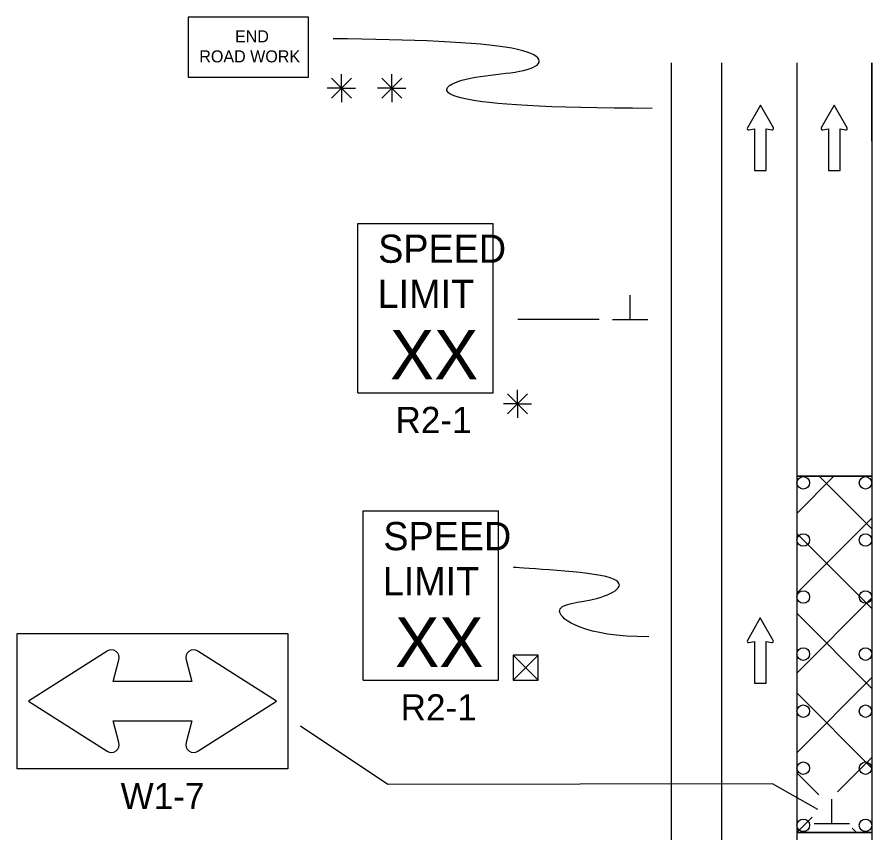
# Model space of a CAD drawing. Extents: x 16732 to 18482, y 5716 to 6919.
# Drawn here: x 16732 to 17004.7, y 6658.6 to 6919 of the extents above; entities that cross this region are included whole.
import ezdxf

# ---------------------------------------------------------------- set-up
doc = ezdxf.new("R2010")
doc.units = 0
for name, color, linetype in [('ALI_LEGAL_EX', 7, 'Continuous'), ('MT_SCRATCH_LEVEL_E', 7, 'Continuous'), ('PAVT_EDGE_EX', 7, 'Continuous'), ('TRAFFIC_SIGNS_PR', 7, 'Continuous'), ('TYPICAL_TEXT_DIMEN_PR', 7, 'Continuous')]:
    doc.layers.add(name, color=color, linetype=linetype)

msp = doc.modelspace()

# ---------------------------------------------------------------- linework, layer by layer
at = {"layer": 'ALI_LEGAL_EX'}
for p, q in [((16980.68, 6904.41), (16980.68, 6086.27)), ((17004.68, 6904.41), (17004.68, 6086.27))]:
    msp.add_line(p, q, dxfattribs=at)
for points in [[(16980.68, 6904.41), (16980.68, 6879.41)], [(17004.68, 6879.41), (17004.68, 6904.41)], [(17004.68, 6879.41), (17004.68, 6904.41)], [(16980.68, 6804.41), (16980.68, 6779.41)], [(17004.68, 6804.41), (17004.68, 6779.41)], [(16980.68, 6704.41), (16980.68, 6679.41)], [(17004.68, 6704.41), (17004.68, 6679.41)]]:
    msp.add_lwpolyline(points, dxfattribs=at)
at = {"layer": 'MT_SCRATCH_LEVEL_E'}
for p, q in [((16969.09, 6890.89), (16964.98, 6883.65)), ((16973.24, 6883.65), (16969.09, 6890.89)), ((16992.64, 6890.89), (16988.53, 6883.65)), ((16996.78, 6883.65), (16992.64, 6890.89)), ((16965.46, 6882.96), (16967.24, 6883.28)), ((16967.24, 6883.28), (16967.24, 6870.02)), ((16970.98, 6870.02), (16970.98, 6883.28)), ((16970.98, 6883.28), (16972.76, 6882.96)), ((16989.01, 6882.96), (16990.78, 6883.28)), ((16990.78, 6883.28), (16990.78, 6870.02)), ((16994.53, 6870.02), (16994.53, 6883.28)), ((16994.53, 6883.28), (16996.3, 6882.96)), ((16967.24, 6870.02), (16970.98, 6870.02)), ((16990.78, 6870.02), (16994.53, 6870.02)), ((16969.06, 6727.27), (16964.95, 6720.03)), ((16973.21, 6720.03), (16969.06, 6727.27)), ((16965.43, 6719.34), (16967.21, 6719.66)), ((16967.21, 6719.66), (16967.21, 6706.4)), ((16970.95, 6706.4), (16970.95, 6719.66)), ((16970.95, 6719.66), (16972.73, 6719.34)), ((16967.21, 6706.4), (16970.95, 6706.4))]:
    msp.add_line(p, q, dxfattribs=at)
for centre, start, end in [((16965.39, 6883.42), 150.4248, 279.9638), ((16972.83, 6883.42), 260.0362, 29.7731), ((16988.93, 6883.42), 150.4248, 279.9638), ((16996.37, 6883.42), 260.0362, 29.7731), ((16965.36, 6719.8), 150.4248, 279.9638), ((16972.8, 6719.8), 260.0362, 29.7731)]:
    msp.add_arc(centre, 0.463, start, end, dxfattribs=at)
at = {"layer": 'PAVT_EDGE_EX'}
for p, q in [((16940.68, 6904.41), (16940.68, 6086.27)), ((16956.68, 6904.41), (16956.68, 6086.27)), ((17004.68, 6772.46), (16980.68, 6772.46)), ((16980.68, 6772.46), (17004.68, 6772.46)), ((16980.68, 6772.46), (17004.68, 6772.46)), ((16980.68, 6760.56), (16992.58, 6772.46)), ((17004.68, 6755.65), (16987.87, 6772.46)), ((16980.68, 6735.1), (17004.68, 6759.1)), ((17004.68, 6730.19), (16980.68, 6754.19)), ((16980.68, 6709.64), (17004.68, 6733.64)), ((17004.68, 6704.74), (16980.68, 6728.74)), ((16980.68, 6684.19), (17004.68, 6708.19)), ((17004.68, 6679.28), (16980.68, 6703.28)), ((16993.7, 6671.75), (17004.68, 6682.73)), ((16987.74, 6670.76), (16980.68, 6677.82)), ((16980.68, 6658.73), (16985.57, 6663.63)), ((16999.77, 6658.73), (16998.36, 6660.14)), ((16980.68, 6658.73), (17004.68, 6658.73)), ((16980.68, 6658.73), (17004.68, 6658.73)), ((17004.68, 6658.73), (16980.68, 6658.73)), ((16980.68, 6658.73), (16980.68, 6658.73))]:
    msp.add_line(p, q, dxfattribs=at)
at = {"layer": 'TRAFFIC_SIGNS_PR'}
for p, q in [((16840.68, 6853.1), (16883.88, 6853.1)), ((16840.68, 6799.1), (16840.68, 6853.1)), ((16883.88, 6799.1), (16883.88, 6853.1)), ((16840.68, 6799.1), (16883.88, 6799.1)), ((16842.32, 6761.37), (16885.52, 6761.37)), ((16842.32, 6707.37), (16842.32, 6761.37)), ((16885.52, 6707.37), (16885.52, 6761.37)), ((16842.32, 6707.37), (16885.52, 6707.37))]:
    msp.add_line(p, q, dxfattribs=at)
for points in [[(16786.49, 6899.8), (16824.89, 6899.8), (16824.89, 6919), (16786.49, 6919)], [(16818.36, 6679.06), (16731.96, 6679.06), (16731.96, 6722.26), (16818.36, 6722.26)]]:
    msp.add_lwpolyline(points, close=True, dxfattribs=at)
for points in [[(16760.67, 6716.64), (16735.56, 6700.66), (16760.67, 6684.68)], [(16789.65, 6684.69), (16814.76, 6700.66), (16789.65, 6716.64)], [(16785.87, 6713.85), (16787.76, 6706.96), (16762.57, 6706.96), (16764.46, 6713.85)], [(16764.46, 6687.48), (16762.57, 6694.36), (16787.76, 6694.36), (16785.87, 6687.48)]]:
    msp.add_lwpolyline(points, dxfattribs=at)
for centre in [(16982.78, 6770.34), (17002.65, 6770.34), (16982.78, 6752.12), (17002.65, 6752.12), (16982.78, 6733.91), (17002.65, 6733.91), (16982.78, 6715.69), (17002.65, 6715.69), (16982.78, 6697.48), (17002.65, 6697.48), (16982.78, 6679.26), (17002.65, 6679.26), (16982.78, 6661.05), (17002.65, 6661.05)]:
    msp.add_circle(centre, 2, dxfattribs=at)
for centre, start, end in [((16762.03, 6714.51), 344.6731, 122.4696), ((16788.3, 6714.51), 57.5304, 195.3269), ((16762.03, 6686.81), 237.5304, 15.3269), ((16788.3, 6686.81), 164.6928, 302.4524)]:
    msp.add_arc(centre, 2.52, start, end, dxfattribs=at)
at = {"layer": 'TYPICAL_TEXT_DIMEN_PR'}
for p, q in [((16835.44, 6896.32), (16835.44, 6900.77)), ((16851.5, 6896.32), (16851.5, 6900.77)), ((16832.25, 6899.51), (16838.63, 6893.13)), ((16838.63, 6899.51), (16832.25, 6893.13)), ((16854.69, 6899.51), (16848.31, 6893.13)), ((16848.32, 6899.51), (16854.69, 6893.13)), ((16835.44, 6896.32), (16830.91, 6896.32)), ((16835.44, 6896.32), (16838.63, 6896.32)), ((16835.44, 6896.32), (16839.92, 6896.32)), ((16835.44, 6896.32), (16835.44, 6891.82)), ((16851.5, 6896.32), (16846.97, 6896.32)), ((16851.5, 6896.32), (16854.69, 6896.32)), ((16851.5, 6896.32), (16855.98, 6896.32)), ((16851.5, 6896.32), (16851.5, 6891.82)), ((16927.55, 6822.46), (16927.55, 6830.24)), ((16917.68, 6822.46), (16891.68, 6822.46)), ((16921.93, 6822.46), (16933.18, 6822.46)), ((16891.64, 6795.54), (16891.64, 6800)), ((16888.45, 6798.73), (16894.83, 6792.35)), ((16894.83, 6798.73), (16888.45, 6792.35)), ((16891.64, 6795.54), (16887.11, 6795.54)), ((16891.64, 6795.54), (16894.83, 6795.54)), ((16891.64, 6795.54), (16896.12, 6795.54)), ((16891.64, 6795.54), (16891.64, 6791.04)), ((16890.19, 6715.37), (16898.19, 6707.37)), ((16890.19, 6707.37), (16898.19, 6715.37)), ((16850.27, 6674.04), (16822.42, 6692.66)), ((16972.92, 6674.29), (16850.27, 6674.04)), ((16987.38, 6666.07), (16972.92, 6674.29)), ((16991.94, 6661.64), (16991.94, 6669.42)), ((16986.31, 6661.64), (16997.56, 6661.64))]:
    msp.add_line(p, q, dxfattribs=at)
msp.add_lwpolyline([(16890.19, 6715.37), (16890.19, 6707.37), (16898.19, 6707.37), (16898.19, 6715.37)], close=True, dxfattribs=at)
for points in [[(16934.56, 6889.87), (16865.56, 6889.87), (16865.56, 6900.62), (16900.47, 6900.62), (16900.47, 6910.28), (16857.61, 6911.81), (16832.82, 6912.06)], [(16933.52, 6721.21), (16912.79, 6721.21), (16898.02, 6731.97), (16918.08, 6731.97), (16932.94, 6741.63), (16890.08, 6743.15), (16890.31, 6743.41)]]:
    msp.add_open_spline(points, degree=3, dxfattribs=at)

# ---------------------------------------------------------------- texts
at = {"layer": 'TRAFFIC_SIGNS_PR'}
for s, height, p in [('END', 3.831, (16801.49, 6910.93)), ('ROAD WORK', 3.831, (16790.1, 6904.54)), ('SPEED', 9, (16847.17, 6840.57)), ('LIMIT', 9, (16846.99, 6826.17)), ('XX', 15.785, (16850.93, 6803.33)), ('R2-1', 8.37, (16852.69, 6786.23)), ('SPEED', 9, (16848.81, 6748.84)), ('LIMIT', 9, (16848.63, 6734.44)), ('XX', 15.785, (16852.57, 6711.59)), ('R2-1', 8.37, (16854.33, 6694.5)), ('W1-7', 8.37, (16764.99, 6666.19))]:
    msp.add_text(s, height=height, dxfattribs=at).set_placement(p)

doc.saveas('drawing.dxf')
